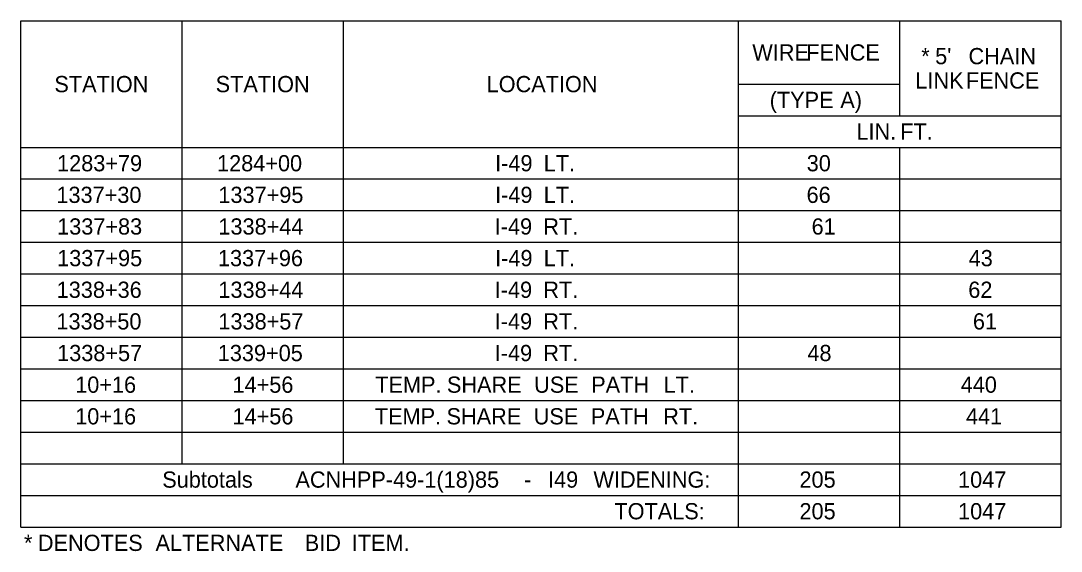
# Model space of a CAD drawing. Extents: x 1226589 to 1228130, y 151309 to 152305.
# Drawn here: x 1227785.6 to 1228106.4, y 151677.4 to 151840.9 of the extents above; entities that cross this region are included whole.
import ezdxf

# ---------------------------------------------------------------- set-up
doc = ezdxf.new("R2010")
doc.units = 0
doc.layers.add('R_Dimension', color=7, linetype='Continuous')

msp = doc.modelspace()

# ---------------------------------------------------------------- linework, layer by layer
at = {"layer": 'R_Dimension'}
for p, q in [((1227785.63, 151840.88), (1228106.4, 151840.88)), ((1227785.63, 151684.88), (1227785.63, 151840.88)), ((1227835.35, 151704.38), (1227835.35, 151840.88)), ((1227885.08, 151704.38), (1227885.08, 151840.88)), ((1228006.95, 151684.88), (1228006.95, 151840.88)), ((1228056.68, 151811.63), (1228056.68, 151840.88)), ((1228106.4, 151684.88), (1228106.4, 151840.88)), ((1228006.95, 151821.38), (1228056.68, 151821.38)), ((1228006.95, 151811.63), (1228106.4, 151811.63)), ((1227785.63, 151801.88), (1228106.4, 151801.88)), ((1228056.68, 151684.88), (1228056.68, 151801.88)), ((1227785.63, 151792.13), (1228106.4, 151792.13)), ((1227785.63, 151782.38), (1228106.4, 151782.38)), ((1227785.63, 151772.63), (1228106.4, 151772.63)), ((1227785.63, 151762.88), (1228106.4, 151762.88)), ((1227785.63, 151753.13), (1228106.4, 151753.13)), ((1227785.63, 151743.38), (1228106.4, 151743.38)), ((1227785.63, 151733.63), (1228106.4, 151733.63)), ((1227785.63, 151723.88), (1228106.4, 151723.88)), ((1227785.63, 151714.13), (1228106.4, 151714.13)), ((1227785.63, 151704.38), (1228106.4, 151704.38)), ((1227785.63, 151694.63), (1228106.4, 151694.63)), ((1227785.63, 151684.88), (1228106.4, 151684.88))]:
    msp.add_line(p, q, dxfattribs=at)

# ---------------------------------------------------------------- texts
for s, p in [('WIRE', (1228011.17, 151828.63)), (' FENCE', (1228025.97, 151828.63)), ('*', (1228063.25, 151827.5)), (" 5'", (1228065.69, 151827.5)), (' CHAIN', (1228075.97, 151827.5)), ('STATION', (1227795.98, 151818.88)), ('STATION', (1227845.71, 151818.88)), ('LOCATION', (1227929.26, 151818.88)), ('LINK', (1228061.44, 151820)), (' FENCE', (1228075.14, 151820)), ('(TYPE', (1228016.52, 151814)), (' A)', (1228036.44, 151814)), ('LIN.', (1228043.27, 151804.25)), (' FT.', (1228054.93, 151804.25)), ('1283+79', (1227796.81, 151794.5)), ('1284+00', (1227846.14, 151794.5)), ('I-49', (1227931.88, 151794.5)), (' LT.', (1227944.99, 151794.5)), ('30', (1228027.94, 151794.5)), ('1337+30', (1227796.61, 151784.75)), ('1337+95', (1227846.55, 151784.75)), ('I-49', (1227931.88, 151784.75)), (' LT.', (1227944.99, 151784.75)), ('66', (1228027.9, 151784.75)), ('1337+83', (1227796.83, 151775)), ('1338+44', (1227846.55, 151775)), ('I-49', (1227931.76, 151775)), (' RT.', (1227944.87, 151775)), ('61', (1228029.45, 151775)), ('1337+95', (1227796.83, 151765.25)), ('1337+96', (1227846.42, 151765.25)), ('I-49', (1227931.88, 151765.25)), (' LT.', (1227944.99, 151765.25)), ('43', (1228077.88, 151765.25)), ('1338+36', (1227796.69, 151755.5)), ('1338+44', (1227846.55, 151755.5)), ('I-49', (1227931.76, 151755.5)), (' RT.', (1227944.87, 151755.5)), ('62', (1228077.76, 151755.5)), ('1338+50', (1227796.61, 151745.75)), ('1338+57', (1227846.55, 151745.75)), ('I-49', (1227931.76, 151745.75)), (' RT.', (1227944.87, 151745.75)), ('61', (1228079.18, 151745.75)), ('1338+57', (1227796.83, 151736)), ('1339+05', (1227846.36, 151736)), ('I-49', (1227931.76, 151736)), (' RT.', (1227944.87, 151736)), ('48', (1228028.15, 151736)), ('10+16', (1227802.4, 151726.25)), ('14+56', (1227850.9, 151726.25)), ('TEMP.', (1227894.91, 151726.25)), (' SHARE', (1227915.15, 151726.25)), (' USE', (1227942.04, 151726.25)), (' PATH', (1227959.64, 151726.25)), (' LT.', (1227981.96, 151726.25)), ('440', (1228075.42, 151726.25)), ('10+16', (1227802.4, 151716.5)), ('14+56', (1227850.9, 151716.5)), ('TEMP.', (1227894.79, 151716.5)), (' SHARE', (1227915.03, 151716.5)), (' USE', (1227941.92, 151716.5)), (' PATH', (1227959.52, 151716.5)), (' RT.', (1227981.84, 151716.5)), ('441', (1228077.05, 151716.5)), ('Subtotals', (1227829.24, 151697)), (' ACNHPP-49-1(18)85', (1227868.45, 151697)), (' I49', (1227946.33, 151697)), (' WIDENING:', (1227960.34, 151697)), ('205', (1228025.71, 151697)), ('1047', (1228074.61, 151697)), (' -', (1227938.89, 151697)), ('TOTALS:', (1227968.65, 151687.25)), ('205', (1228025.71, 151687.25)), ('1047', (1228074.61, 151687.25)), ('*', (1227786.6, 151677.5)), (' DENOTES', (1227789.04, 151677.5)), (' ALTERNATE', (1227825.3, 151677.5)), (' BID', (1227871.33, 151677.5)), (' ITEM.', (1227885.81, 151677.5))]:
    msp.add_text(s, height=5, dxfattribs=at).set_placement(p)

doc.saveas('drawing.dxf')
